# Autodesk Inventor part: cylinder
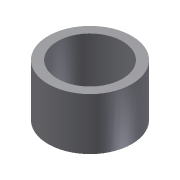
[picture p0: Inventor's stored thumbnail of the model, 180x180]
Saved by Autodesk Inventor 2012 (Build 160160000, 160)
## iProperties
Shininess: 64.0
Length Units: 11269
Angle Units: 11279
Time Units: 11290
Mass Units: 11283
Length Display Precision: 3
Angle Display Precision: 2
Compacted: True
Part Number: cylinder
Document SubType Name: Modeling
Created: 2003-01
Designer: Owner
Density: 1 g/cm^3
Material: Default
Density: 0.0
Volumn: 0.0
Area: 0.0
PropertySet Name: Model Information
Control State: 0
Master: False
Checked Out: False
Author: Owner
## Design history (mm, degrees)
sketch "Sketch1"
  geometry: C1 r 112.5 at (0, 0); C2 r 87.5 at (0, 0)
  constraints: 2 centre point, 1 coincident, 1 concentric
  dimensions: "d0" = 225 diameter of C1; "d1" = 175 diameter of C2
extrude "Extrusion1" new body sketch "Sketch1" stored distance "d2" = 140; taper "d3" = 0 deg
body "Solid1"
